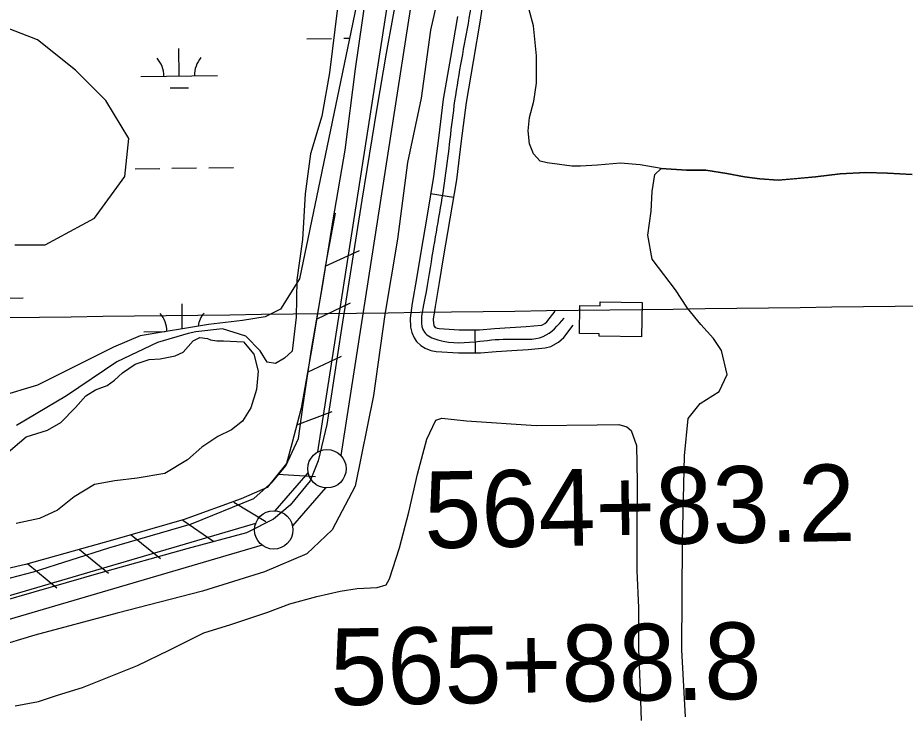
# Model space of a CAD drawing. Extents: x 3715084 to 3753216, y 488173 to 513963.
# Drawn here: x 3735343 to 3736499, y 499333 to 500239 of the extents above; entities that cross this region are included whole.
import ezdxf

# ---------------------------------------------------------------- set-up
doc = ezdxf.new("R2010")
doc.units = 0
for name, color, linetype in [('V-BLDG-OTLN', 7, 'Continuous'), ('V-FLOD-BASE', 7, 'Continuous'), ('V-GRID-MAJR', 7, 'Continuous'), ('V-LEVE-TOET', 7, 'Continuous'), ('V-ROAD-CNTR', 7, 'Continuous'), ('V-RRAP-FSHR', 7, 'Continuous'), ('V-SITE-VEGE', 7, 'Continuous'), ('V-SURV-IDEN', 7, 'Continuous'), ('V-SURV-LINE', 7, 'Continuous'), ('V-TOPO-SHOR', 7, 'Continuous'), ('V-WETL-SWMP', 7, 'Continuous')]:
    doc.layers.add(name, color=color, linetype=linetype)

msp = doc.modelspace()

# ---------------------------------------------------------------- linework, layer by layer
at = {"layer": 'V-BLDG-OTLN'}
msp.add_lwpolyline([(3736155.8850000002, 499868.177), (3736155.228, 499823.322), (3736100.083, 499824.131), (3736100.132, 499827.482), (3736074.514, 499827.856), (3736075.048, 499864.411), (3736101.427, 499864.02400000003), (3736101.5, 499868.976)], close=True, dxfattribs=at)
at = {"layer": 'V-FLOD-BASE'}
msp.add_lwpolyline([(3735839.111, 500283.788), (3735822.643, 500192.773), (3735810.6070000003, 500121.351), (3735790.966, 500001.26), (3735764.359, 499834.398), (3735745.349, 499709.248), (3735733.954, 499661.84500000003), (3735723.8310000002, 499635.934), (3735697.903, 499604.338), (3735675.774, 499586.016), (3735641.001, 499568.33), (3735563.247, 499547.499), (3735448.1950000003, 499515.305), (3735321.761, 499478.689)], dxfattribs=at)
at = {"layer": 'V-GRID-MAJR'}
msp.add_spline([(3719277.161, 499651.167), (3724559.356, 499715.322), (3729841.541, 499780.245), (3735123.717, 499845.93700000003), (3740405.883, 499912.396), (3745688.039, 499979.624), (3750970.185, 500047.621), (3750970.186, 500047.621)], degree=3, dxfattribs=at)
at = {"layer": 'V-LEVE-TOET'}
for points in [[(3735898.785, 500303.574), (3735880.64, 500222.993), (3735868.112, 500134.29000000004), (3735850.592, 500050.587), (3735837.435, 499950.64), (3735821.1580000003, 499852.568), (3735806.126, 499746.999), (3735782.344, 499628.938), (3735752.339, 499572.102), (3735719.217, 499540.88), (3735664.236, 499517.16000000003), (3735583.639, 499492.20300000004)], [(3735312.969, 499504.33400000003), (3735363.575, 499517.435), (3735461.664, 499548.632), (3735569.125, 499579.829), (3735650.346, 499612.908), (3735674.72, 499634.765), (3735692.218, 499655.374), (3735708.473, 499690.974), (3735714.736, 499734.701), (3735725.383, 499807.163), (3735739.781, 499888.993), (3735753.555, 499975.822), (3735769.2060000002, 500066.397), (3735782.989, 500172.592), (3735796.7660000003, 500268.791)], [(3735583.639, 499492.20300000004), (3735472.433, 499463.507), (3735364.972, 499434.81), (3735261.261, 499403.613)]]:
    msp.add_lwpolyline(points, dxfattribs=at)
at = {"layer": 'V-ROAD-CNTR'}
for p, q in [((3735910.247140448, 500004.77096434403), (3735880.649199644, 500009.6689545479)), ((3735938.193084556, 499832.695308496), (3735938.599083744, 499802.69836849))]:
    msp.add_line(p, q, dxfattribs=at)
for points in [[(3735961.508037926, 500347.73327841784), (3735945.3340702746, 500235.99850188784), (3735936.0270888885, 500182.074609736), (3735926.7351074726, 500128.73771640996), (3735920.5791197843, 500078.70281647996), (3735914.1011327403, 500028.0569177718), (3735905.652149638, 499977.00701987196), (3735897.144166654, 499926.2281214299), (3735891.730177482, 499894.41918504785), (3735886.3121883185, 499862.8212482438), (3735883.9531930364, 499846.6402806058), (3735884.297192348, 499840.65529257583), (3735884.7881913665, 499838.7672963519), (3735885.754189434, 499836.55030078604), (3735885.659189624, 499836.6973004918), (3735886.549187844, 499835.82630223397), (3735886.803187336, 499835.66930254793), (3735888.953183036, 499834.85130418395), (3735891.7571774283, 499834.33030522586), (3735917.7581254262, 499832.41830904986), (3735944.1520726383, 499832.7763083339), (3735963.9370330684, 499834.1223056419), (3735984.129992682, 499835.53830281), (3736005.0079509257, 499837.005299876), (3736024.844911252, 499838.81629625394), (3736026.098908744, 499839.1062956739), (3736029.509901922, 499841.01429185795), (3736031.7968973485, 499843.09428769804), (3736042.678875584, 499857.097259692)], [(3735915.702129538, 500240.6984924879), (3735906.469148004, 500187.200599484), (3735897.0511668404, 500133.14570759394), (3735890.813179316, 500082.43680901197), (3735884.4131921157, 500032.4109090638), (3735876.060208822, 499981.93501001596), (3735867.562225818, 499931.2241114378), (3735862.158236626, 499899.47117494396), (3735856.6802475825, 499867.5212388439), (3735853.827253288, 499847.9562779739), (3735854.5172519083, 499835.9773019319), (3735856.344248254, 499828.9413160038), (3735859.23624247, 499822.3083292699), (3735862.2932363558, 499817.587338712), (3735867.939225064, 499812.0643497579), (3735873.4512140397, 499808.65135658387), (3735880.813199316, 499805.84936218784), (3735887.9071851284, 499804.53236482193), (3735916.8601272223, 499802.40436907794), (3735945.3740701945, 499802.7903683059), (3735966.0050289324, 499804.19436549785), (3735986.227988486, 499805.61236266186), (3736007.4219460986, 499807.101359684), (3736029.618901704, 499809.126355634), (3736037.024886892, 499810.8443521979), (3736047.151866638, 499816.5083408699), (3736053.896853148, 499822.64232860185), (3736066.366828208, 499838.68929650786)]]:
    msp.add_lwpolyline(points, dxfattribs=at)
for points in [[(3736012.6309356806, 500795.612382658), (3736013.5709337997, 500791.5633907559), (3736018.123924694, 500746.36248115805), (3736008.69594355, 500679.7906143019), (3735984.686991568, 500602.507768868), (3735962.5790357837, 500461.4270510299), (3735930.518099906, 500238.34849718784), (3735911.893137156, 500130.9417120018), (3735899.257162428, 500030.23391341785), (3735882.3531962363, 499928.72611643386), (3735871.49621795, 499865.17124354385), (3735872.495215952, 499829.42931502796), (3735889.832181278, 499819.4313350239), (3735944.763071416, 499817.78333832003), (3735985.1789905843, 499820.575332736), (3736027.231906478, 499823.97132594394), (3736054.5228518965, 499847.8932781)], [(3733715.5725298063, 498954.1440656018), (3733927.4081061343, 498985.4220030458), (3734149.04466286, 499017.4349390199), (3734317.1243267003, 499039.17989553), (3734452.533055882, 499051.021871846), (3734616.6037277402, 499062.12884963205), (3734803.4543540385, 499064.3688451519), (3734911.8351372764, 499064.8078442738), (3735132.1146967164, 499070.0368338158), (3735323.316314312, 499078.37181714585), (3735505.803949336, 499097.111779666), (3735898.0601648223, 499142.646688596), (3736237.231486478, 499184.4396050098), (3736547.3718661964, 499225.4965228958), (3736808.1873445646, 499257.56445876), (3736976.362008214, 499281.2394114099), (3737080.0268008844, 499296.4683809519), (3737176.0426088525, 499320.73933240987), (3737239.9724809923, 499343.32428724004), (3737319.351322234, 499377.88521811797), (3737388.8621832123, 499415.7931423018), (3737461.5770377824, 499455.86406216), (3737533.711893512, 499510.0739537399), (3737613.734733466, 499584.10580567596), (3737686.298588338, 499661.42465103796), (3737745.2314704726, 499744.2114854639), (3737793.210374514, 499828.8213162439), (3737831.048298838, 499907.621158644), (3737863.2922343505, 499993.6939864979), (3737884.48719196, 500070.0438337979), (3737902.013156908, 500150.4446729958), (3737918.8031233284, 500240.6464925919), (3737947.8120653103, 500405.0821637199), (3737975.5520098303, 500525.3699231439)]]:
    msp.add_spline(points, degree=3, dxfattribs=at)
at = {"layer": 'V-RRAP-FSHR'}
for p, q in [((3735743.286, 499915.701), (3735787.833, 499935.7)), ((3735732.098, 499846.598), (3735776.109, 499867.75200000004)), ((3735720.386, 499777.586), (3735764.623, 499798.262)), ((3735706.5530000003, 499709.016), (3735752.292, 499726.114)), ((3735681.825, 499644.74100000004), (3735730.536, 499641.332)), ((3735624.1210000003, 499608.238), (3735665.832, 499582.847)), ((3735558.131, 499584.814), (3735598.176, 499556.871)), ((3735490.794, 499565.673), (3735528.722, 499534.917)), ((3735423.441, 499546.608), (3735461.236, 499515.689)), ((3735356.057, 499527.648), (3735393.853, 499496.729))]:
    msp.add_line(p, q, dxfattribs=at)
msp.add_lwpolyline([(3735756.429, 499984.456), (3735744.455, 499921.818), (3735726.3030000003, 499811.321), (3735712.16, 499730.693), (3735700.048, 499683.871), (3735692.829, 499658.329), (3735667.7490000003, 499627.36100000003), (3735634.003, 499612.569), (3735559.603, 499585.353), (3735466.1750000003, 499558.632), (3735353.1750000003, 499526.837), (3735249.6780000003, 499502.966)], dxfattribs=at)
at = {"layer": 'V-SITE-VEGE'}
for points in [[(3735759.153, 500252.108), (3735748.937, 500167.445), (3735738.7320000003, 500110.794), (3735724.0700000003, 500061.783), (3735717.0500000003, 500009.586), (3735713.845, 499950.384), (3735706.185, 499897.554)], [(3736212.5670000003, 499328.64), (3736207.673, 499415.68), (3736208.545, 499556.91000000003), (3736211.0500000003, 499668.581), (3736215.9960000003, 499717.027), (3736231.6040000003, 499736.726), (3736256.241, 499752.32), (3736266.926, 499774.485), (3736259.5470000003, 499805.691), (3736248.876, 499821.297), (3736232.4620000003, 499839.36600000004), (3736215.2260000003, 499860.721), (3736199.634, 499884.541), (3736169.267, 499924.784), (3736163.5300000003, 499955.989), (3736167.649, 499987.191), (3736169.301, 500012.645), (3736172.593, 500034.815), (3736180.801, 500042.61600000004), (3736213.669, 500040.707), (3736238.9560000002, 500040.697), (3736266.1350000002, 500036.26300000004), (3736289.521, 500031.829), (3736309.116, 500029.294), (3736333.1350000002, 500027.389), (3736381.81, 500031.794), (3736414.0500000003, 500035.577), (3736447.5530000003, 500037.461), (3736475.367, 500036.818), (3736507.6040000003, 500034.909)], [(3735706.185, 499897.554), (3735705.534, 499849.172), (3735700.424, 499804.614), (3735690.235, 499795.705), (3735678.775, 499788.70900000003), (3735667.953, 499790.62), (3735658.409, 499805.265), (3735639.957, 499824.369), (3735609.4050000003, 499833.929), (3735575.0270000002, 499830.121), (3735564.84, 499827.58), (3735524.7320000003, 499816.136), (3735471.8880000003, 499790.691), (3735406.3030000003, 499746.792), (3735341.356, 499707.985)], [(3735826.89, 499508.315), (3735840.094, 499548.446), (3735852.15, 499594.884), (3735863.637, 499644.761), (3735875.694, 499690.053), (3735887.171, 499714.704), (3735895.197, 499717.56700000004), (3735927.308, 499714.117), (3736017.895, 499707.776), (3736097.593, 499708.892), (3736125.687, 499709.455), (3736136.007, 499706.01300000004), (3736141.739, 499701.42100000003), (3736148.613, 499681.92600000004), (3736149.741, 499634.337), (3736149.147, 499575.854), (3736149.127, 499519.092), (3736151.4020000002, 499470.353), (3736151.381, 499417.032), (3736153.657, 499362.561), (3736154.787, 499323.571)], [(3735339.47, 499342.792), (3735369.863, 499348.514), (3735394.518, 499356.532), (3735427.205, 499366.83900000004), (3735498.887, 499395.483), (3735540.176, 499415.53500000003), (3735585.478, 499437.878), (3735620.458, 499448.759), (3735668.627, 499464.797), (3735697.301, 499475.68200000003), (3735732.281, 499485.414), (3735762.669, 499492.283), (3735785.0330000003, 499495.716), (3735810.8340000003, 499496.854), (3735822.876, 499500.289), (3735826.89, 499508.315)]]:
    msp.add_lwpolyline(points, dxfattribs=at)
at = {"layer": 'V-SURV-LINE'}
for points in [[(3735733.837496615, 499673.6432789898), (3735892.443927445, 500693.4535452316)], [(3735922.089635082, 500688.85656779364), (3735763.483090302, 499669.0455688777)], [(3735678.1222579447, 499596.90718833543), (3735721.164777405, 499646.3811986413)], [(3735743.790810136, 499626.6818899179), (3735700.7478975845, 499577.20742778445)], [(3735136.714858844, 499429.16287793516), (3735652.9176061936, 499580.7463425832)], [(3735661.385099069, 499551.96610970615), (3735145.1824448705, 499400.3826724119)]]:
    msp.add_lwpolyline(points, dxfattribs=at)
for centre in [(3735745.58967, 499651.60334999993), (3735676.3229, 499571.98575)]:
    msp.add_circle(centre, 25, dxfattribs=at)
at = {"layer": 'V-TOPO-SHOR'}
for points in [[(3736507.6040000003, 500034.909), (3736475.367, 500036.818), (3736447.5530000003, 500037.461), (3736414.0500000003, 500035.577), (3736381.81, 500031.794), (3736353.9960000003, 500029.277), (3736333.1350000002, 500027.389), (3736309.116, 500029.294), (3736289.521, 500031.829), (3736266.1350000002, 500036.26300000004), (3736238.9560000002, 500040.697), (3736213.669, 500040.707), (3736180.801, 500042.61600000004), (3736153.622, 500047.68), (3736127.705, 500049.587), (3736097.994, 500047.07), (3736075.87, 500045.815), (3736064.4930000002, 500045.819), (3736032.255, 500050.255), (3736023.406, 500052.153), (3736014.561, 500061.64), (3736009.508, 500074.91500000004), (3736007.6180000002, 500091.983), (3736009.521, 500109.05100000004), (3736015.216, 500130.54000000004), (3736018.386, 500153.927), (3736018.401, 500189.326), (3736014.62, 500228.51900000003), (3736008.941, 500249.382)], [(3735324.602, 499668.368), (3735353.687, 499693.01), (3735381.503, 499701.849), (3735399.2060000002, 499711.958), (3735418.177, 499731.545), (3735431.4560000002, 499746.713), (3735444.103, 499754.292), (3735459.274, 499759.97500000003), (3735468.761, 499766.92600000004), (3735479.508, 499776.40400000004), (3735495.948, 499787.777), (3735514.281, 499794.091), (3735528.1890000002, 499794.718), (3735547.787, 499798.50200000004), (3735558.535, 499803.55700000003), (3735571.181, 499818.08900000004), (3735580.032, 499822.511), (3735590.145, 499821.243), (3735593.938, 499819.347), (3735602.1550000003, 499818.079), (3735611.004, 499818.075)], [(3735611.004, 499818.075), (3735636.9220000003, 499816.80100000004), (3735650.191, 499800.995), (3735655.872, 499778.868), (3735653.965, 499754.847), (3735646.3710000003, 499730.83), (3735635.619, 499713.766), (3735621.076, 499702.39400000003), (3735603.3740000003, 499693.55100000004), (3735582.508, 499679.653), (3735564.173, 499663.224), (3735534.454, 499645.53500000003), (3735498.4220000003, 499639.227), (3735469.344, 499636.07800000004), (3735442.794, 499631.02900000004), (3735416.238, 499615.237), (3735394.74, 499597.544), (3735371.347, 499586.809), (3735341.002, 499580.499)]]:
    msp.add_lwpolyline(points, dxfattribs=at)
at = {"layer": 'V-WETL-SWMP'}
for p, q in [((3735719.5956461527, 500211.74275306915), (3735751.5931475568, 500212.14263293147)), ((3735767.591898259, 500212.34257286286), (3735774.99315684, 500212.4350680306)), ((3735553.124891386, 500163.22870558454), (3735552.6750265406, 500199.2258946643)), ((3735503.1287954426, 500162.6038932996), (3735603.1209873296, 500163.85351786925)), ((3735541.3186579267, 500147.6489555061), (3735565.3167839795, 500147.94886540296)), ((3735495.7859227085, 500042.4317517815), (3735527.7834241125, 500042.83163164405)), ((3735543.782174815, 500043.03157157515), (3735575.7796762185, 500043.4314514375)), ((3735591.778426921, 500043.63139136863), (3735623.7759283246, 500044.03127123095)), ((3735317.876528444, 499874.0214026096), (3735349.8740298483, 499874.4212824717)), ((3735557.2387586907, 499834.04615037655), (3735556.832215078, 499866.57687030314)), ((3735507.2859839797, 499829.9548689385), (3735534.7496266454, 499830.29808816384))]:
    msp.add_line(p, q, dxfattribs=at)
for points in [[(3735773.906, 501025.255), (3735783.786, 500921.518), (3735838.1240000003, 500768.38300000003), (3735848.004, 500635.00800000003), (3735808.485, 500373.197), (3735709.6890000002, 499898.973), (3735684.99, 499859.454), (3735665.23, 499849.575), (3735635.591, 499844.635), (3735591.133, 499839.695), (3735502.216, 499824.876), (3735467.637, 499810.056), (3735368.84, 499760.658), (3735270.044, 499731.01900000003)], [(3735339.201, 499943.43200000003), (3735378.72, 499943.43200000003), (3735442.938, 499978.01), (3735482.4560000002, 500032.349), (3735487.396, 500081.74700000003), (3735457.757, 500131.145), (3735418.239, 500170.664), (3735368.84, 500210.18200000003), (3735304.623, 500234.882)]]:
    msp.add_lwpolyline(points, dxfattribs=at)
for centre, radius, start, end in [((3735497.880335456, 500163.0131423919), 35.24628790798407, 359.94418071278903, 41.48783904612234), ((3735608.3575808, 500164.393800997), 35.246287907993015, 139.9441777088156, 181.48783604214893), ((3735502.0375239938, 499830.3641180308), 35.24628790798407, 0.578750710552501, 41.48783904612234), ((3735612.5147693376, 499831.7447766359), 35.246287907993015, 139.94417770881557, 170.6647295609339)]:
    msp.add_arc(centre, radius, start, end, dxfattribs=at)

# ---------------------------------------------------------------- texts
at = {"layer": 'V-SURV-IDEN'}
for s, rotation, p in [('564+83.2', 1.0045917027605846, (3735872.889193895, 499547.88978949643)), ('565+88.8', 0.8726719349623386, (3735750.416476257, 499343.40028345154))]:
    msp.add_text(s, height=99.99999999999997, rotation=rotation, dxfattribs=at).set_placement(p)

doc.saveas('drawing.dxf')
